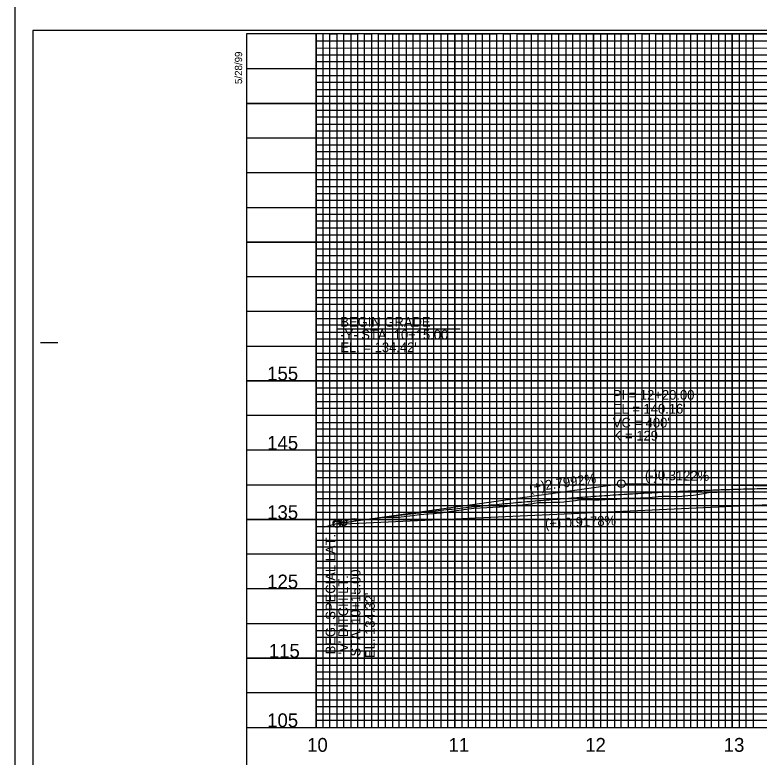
# Model space of a CAD drawing. Extents: x 573468 to 580768, y -57414 to -51768.
# Drawn here: x 578678 to 579215, y -54660 to -54125 of the extents above; entities that cross this region are included whole.
import ezdxf

# ---------------------------------------------------------------- set-up
doc = ezdxf.new("R2010")
doc.units = 0
for name, color, linetype in [('Exist Vertical Profile Ground Line', 7, 'Continuous'), ('Exist Vertical Profile Horizontal Axis Label Major', 7, 'Continuous'), ('Exist Vertical Profile Vertical Axis Label', 7, 'Continuous'), ('Prop Grid Mask', 7, 'Continuous'), ('Prop PFL Text', 7, 'Continuous'), ('Prop Vertical Profile Curve Label', 7, 'Continuous'), ('Prop Vertical Profile Ditch Grade Left', 7, 'Continuous'), ('Prop Vertical Profile Ditch Grade Left Label', 7, 'Continuous'), ('Prop Vertical Profile Grade', 7, 'Continuous'), ('Prop Vertical Profile Grade Label', 7, 'Continuous'), ('Prop VPI Label', 7, 'Continuous'), ('Sheet Cutting Line CELL', 7, 'Continuous'), ('Sheet DOT Grid CELL', 7, 'Continuous'), ('Sheet Layout Profile Border Port 1', 7, 'Continuous'), ('Sheet Plot Border Inside CELL', 7, 'Continuous'), ('Sheet Plot Border Outside CELL', 7, 'Continuous'), ('Sheet Profile CELL', 7, 'Continuous'), ('Sheet Profile Grid Major CELL', 7, 'Continuous'), ('Sheet Profile Grid Middle CELL', 7, 'Continuous'), ('Sheet Profile Grid Minor CELL', 7, 'Continuous')]:
    doc.layers.add(name, color=color, linetype=linetype)

msp = doc.modelspace()

# ---------------------------------------------------------------- linework, layer by layer
at = {"layer": 'Exist Vertical Profile Ground Line'}
msp.add_lwpolyline([(578895.21, -54493.46), (578895.85, -54493.47), (578901.67, -54493.94), (578908.48, -54491.97), (578920.94, -54488.12), (578922.63, -54487.88), (578926.71, -54488.36), (578933.83, -54487.97), (578936.58, -54487.74), (578938.64, -54487.62), (578939.29, -54487.52), (578942.98, -54486.97), (578954.34, -54486.84), (578964.93, -54485.71), (578969.46, -54485.07), (578979.55, -54484.18), (578984.58, -54483.76), (578986.86, -54483.62), (578992.92, -54482.56), (579008.86, -54480.34), (579018.41, -54479.87), (579022.67, -54479.67), (579026.92, -54479.46), (579027.71, -54479.42), (579030.86, -54479.24), (579031.18, -54479.19), (579034.6, -54478.75), (579035.43, -54478.67), (579039.68, -54478.28), (579043.94, -54477.88), (579048.19, -54477.48), (579050.77, -54477.24), (579052.45, -54476.9), (579055.59, -54476.26), (579056.7, -54476.25), (579060.96, -54476.19), (579065.21, -54476.13), (579069.46, -54476.07), (579070.81, -54476.05), (579073.72, -54475.73), (579077.97, -54475.28), (579079.81, -54475.08), (579082.23, -54474.75), (579085.92, -54474.26), (579086.48, -54474.26), (579087.34, -54474.25), (579090.13, -54474.23), (579090.74, -54474.25), (579094.99, -54474.36), (579096.22, -54474.39), (579099.24, -54474.29), (579101.58, -54474.21), (579103.5, -54474.15), (579107.75, -54474.02), (579111.34, -54473.91), (579112.01, -54473.86), (579115.05, -54473.6), (579116.26, -54473.35), (579116.95, -54473.21), (579120.52, -54473.21), (579124.77, -54473.21), (579125.98, -54473.21), (579129.02, -54473.05), (579131.17, -54472.94), (579133.28, -54472.85), (579133.85, -54472.83), (579137.53, -54472.46), (579141.79, -54472.04), (579145.34, -54471.69), (579146.04, -54471.7), (579150.3, -54471.8), (579154.55, -54471.89), (579156.1, -54471.93), (579158.8, -54471.68), (579163.06, -54471.29), (579167.31, -54470.91), (579168.97, -54470.76), (579171.57, -54470.32), (579175.82, -54469.6), (579179.08, -54468.86), (579180.08, -54468.84), (579184.33, -54468.76), (579188.58, -54468.69), (579190.03, -54468.66), (579192.84, -54468.67), (579197.09, -54468.68), (579201.35, -54468.69), (579202.27, -54468.7), (579205.6, -54468.58), (579209.86, -54468.44), (579211.27, -54468.39), (579214.11, -54468.59), (579218.36, -54468.89)], dxfattribs=at)
at = {"layer": 'Prop Grid Mask'}
msp.add_lwpolyline([(579095.21, -54388.55), (579195.21, -54388.55), (579195.21, -54438.55), (579095.21, -54438.55)], close=True, dxfattribs=at)
at = {"layer": 'Prop PFL Text'}
for q in [(578999.13, -54351.04), (578910.21, -54488.68)]:
    msp.add_line((578910.21, -54351.04), q, dxfattribs=at)
at = {"layer": 'Prop Vertical Profile Curve Label'}
msp.add_circle((578915.21, -54490.73), 2.25, dxfattribs=at)
at = {"layer": 'Prop Vertical Profile Ditch Grade Left'}
msp.add_line((578910.21, -54491.95), (579275.21, -54475.2), dxfattribs=at)
at = {"layer": 'Prop Vertical Profile Ditch Grade Left Label'}
msp.add_line((578910.21, -54491.95), (578910.21, -54587.95), dxfattribs=at)
msp.add_circle((578910.21, -54491.95), 2.25, dxfattribs=at)
at = {"layer": 'Prop Vertical Profile Grade'}
msp.add_line((578910.21, -54491.43), (578915.21, -54490.73), dxfattribs=at)
msp.add_spline([(578915.21, -54490.73), (578923.21, -54489.63), (578931.21, -54488.54), (578939.21, -54487.49), (578947.21, -54486.45), (578955.21, -54485.45), (578963.21, -54484.46), (578971.21, -54483.51), (578979.21, -54482.57), (578987.21, -54481.66), (578995.21, -54480.78), (579003.21, -54479.92), (579011.21, -54479.09), (579019.21, -54478.28), (579027.21, -54477.5), (579035.21, -54476.74), (579043.21, -54476), (579051.21, -54475.3), (579059.21, -54474.61), (579067.21, -54473.95), (579075.21, -54473.32), (579083.21, -54472.71), (579091.21, -54472.12), (579099.21, -54471.56), (579107.21, -54471.03), (579115.21, -54470.52), (579123.21, -54470.03), (579131.21, -54469.57), (579139.21, -54469.14), (579147.21, -54468.73), (579155.21, -54468.34), (579163.21, -54467.98), (579171.21, -54467.65), (579179.21, -54467.34), (579187.21, -54467.05), (579195.21, -54466.79), (579203.21, -54466.55), (579211.21, -54466.34), (579219.21, -54466.16), (579227.21, -54465.99), (579235.21, -54465.86), (579243.21, -54465.75), (579251.21, -54465.66), (579259.21, -54465.6), (579267.21, -54465.56), (579275.21, -54465.55), (579283.21, -54465.56), (579291.21, -54465.6), (579299.21, -54465.66), (579307.21, -54465.75), (579315.21, -54465.86)], degree=3, dxfattribs=at)
at = {"layer": 'Prop VPI Label'}
for p, q in [((578915.21, -54490.73), (579112.49, -54463.12)), ((579315.21, -54465.86), (579117.96, -54462.78))]:
    msp.add_line(p, q, dxfattribs=at)
for centre in [(579115.21, -54462.74), (578910.21, -54491.43)]:
    msp.add_circle(centre, 2.75, dxfattribs=at)
at = {"layer": 'Sheet Cutting Line CELL'}
msp.add_line((578678.21, -54113.55), (578678.21, -55213.55), dxfattribs=at)
at = {"layer": 'Sheet DOT Grid CELL'}
for p, q in [((578895.21, -54638.55), (578895.21, -54138.55)), ((578945.21, -54638.55), (578945.21, -54138.55)), ((578995.21, -54638.55), (578995.21, -54138.55)), ((579045.21, -54638.55), (579045.21, -54138.55)), ((579095.21, -54638.55), (579095.21, -54138.55)), ((579145.21, -54638.55), (579145.21, -54138.55)), ((579195.21, -54638.55), (579195.21, -54138.55)), ((580145.16, -54188.55), (578845.21, -54188.55)), ((580145.16, -54238.55), (578845.21, -54238.55)), ((580345.21, -54288.55), (578845.21, -54288.55)), ((580345.21, -54338.55), (578845.21, -54338.55)), ((580345.21, -54388.55), (578845.21, -54388.55)), ((580345.21, -54438.55), (578845.21, -54438.55)), ((580345.21, -54488.55), (578845.21, -54488.55)), ((580345.21, -54538.55), (578845.21, -54538.55)), ((580345.21, -54588.55), (578845.21, -54588.55))]:
    msp.add_line(p, q, dxfattribs=at)
at = {"layer": 'Sheet Layout Profile Border Port 1'}
msp.add_lwpolyline([(578895.21, -54138.55), (578895.21, -54638.55), (580295.21, -54638.55), (580295.21, -54276.1), (580145.16, -54276.1), (580145.16, -54138.55)], close=True, dxfattribs=at)
at = {"layer": 'Sheet Plot Border Inside CELL'}
msp.add_lwpolyline([(578691.21, -55191.1), (580357.71, -55191.1), (580357.71, -54136), (578691.21, -54136)], close=True, dxfattribs=at)
at = {"layer": 'Sheet Plot Border Outside CELL'}
msp.add_lwpolyline([(578678.21, -55213.55), (580362.21, -55213.55), (580362.21, -54113.55), (578678.21, -54113.55)], close=True, dxfattribs=at)
at = {"layer": 'Sheet Profile CELL'}
for p, q in [((578696.71, -54361.05), (578709.21, -54361.05)), ((578845.21, -54638.55), (580345.21, -54638.55))]:
    msp.add_line(p, q, dxfattribs=at)
msp.add_lwpolyline([(580345.21, -54138.55), (578845.21, -54138.55), (578845.21, -55188.55), (580345.21, -55188.55)], close=True, dxfattribs=at)
at = {"layer": 'Sheet Profile Grid Major CELL'}
for points in [[(578895.21, -54138.55), (578895.21, -54638.55), (578945.21, -54638.55), (578945.21, -54138.55), (578995.21, -54138.55), (578995.21, -54638.55), (579045.21, -54638.55), (579045.21, -54138.55), (579095.21, -54138.55), (579095.21, -54638.55), (579145.21, -54638.55), (579145.21, -54138.55), (579195.21, -54138.55), (579195.21, -54638.55), (579245.21, -54638.55)], [(578845.21, -54188.55), (580145.21, -54188.55)], [(580145.21, -54238.55), (578845.21, -54238.55), (578845.21, -54288.55), (580345.21, -54288.55)], [(580345.21, -54338.55), (578845.21, -54338.55), (578845.21, -54388.55), (580345.21, -54388.55)], [(580345.21, -54438.55), (578845.21, -54438.55), (578845.21, -54488.55), (580345.21, -54488.55)], [(580345.21, -54538.55), (578845.21, -54538.55), (578845.21, -54538.55), (578845.21, -54588.55), (580345.21, -54588.55)]]:
    msp.add_lwpolyline(points, dxfattribs=at)
at = {"layer": 'Sheet Profile Grid Middle CELL'}
msp.add_line((578845.21, -54163.55), (580145.16, -54163.55), dxfattribs=at)
for points in [[(578920.21, -54138.55), (578920.21, -54638.55), (578970.21, -54638.55), (578970.21, -54138.55), (579020.21, -54138.55), (579020.21, -54638.55), (579070.21, -54638.55), (579070.21, -54138.55), (579120.21, -54138.55), (579120.21, -54638.55), (579170.21, -54638.55), (579170.21, -54138.55), (579220.21, -54138.55)], [(580145.21, -54213.55), (578845.21, -54213.55), (578845.21, -54263.55), (580145.21, -54263.55)], [(580345.21, -54313.55), (578845.21, -54313.55), (578845.21, -54363.55), (580170.21, -54363.55)], [(580345.21, -54413.55), (578845.21, -54413.55), (578845.21, -54463.55), (580345.21, -54463.55)], [(580345.21, -54513.55), (578845.21, -54513.55), (578845.21, -54563.55), (580345.21, -54563.55)], [(580345.21, -54613.55), (578845.21, -54613.55)]]:
    msp.add_lwpolyline(points, dxfattribs=at)
at = {"layer": 'Sheet Profile Grid Minor CELL'}
for p, q in [((578895.21, -54143.55), (580145.21, -54143.55)), ((578895.21, -54148.55), (578895.21, -54148.55)), ((580145.21, -54148.55), (578895.21, -54148.9)), ((578895.21, -54153.55), (580145.21, -54153.55)), ((580145.16, -54273.55), (578895.21, -54273.55)), ((580295.21, -54278.55), (578895.21, -54278.55)), ((580295.21, -54283.55), (578895.21, -54283.55)), ((578895.21, -54293.55), (580295.21, -54293.55)), ((580295.21, -54298.55), (578895.21, -54298.55)), ((578895.21, -54303.55), (580295.21, -54303.55)), ((580295.21, -54323.55), (578895.21, -54323.55)), ((578895.21, -54328.55), (580295.21, -54328.55)), ((580295.21, -54348.55), (578895.21, -54348.55)), ((578895.21, -54353.55), (580295.21, -54353.55)), ((580295.21, -54373.55), (578895.21, -54373.55)), ((578895.21, -54378.55), (580295.21, -54378.55)), ((580295.21, -54383.55), (578895.21, -54383.55)), ((578895.21, -54393.55), (580295.21, -54393.55)), ((580295.21, -54398.55), (578895.21, -54398.55)), ((578895.21, -54403.55), (580295.21, -54403.55)), ((580295.21, -54408.55), (578895.21, -54408.55)), ((578895.21, -54418.55), (580295.21, -54418.55)), ((580295.21, -54423.55), (578895.21, -54423.55)), ((578895.21, -54428.55), (580295.21, -54428.55)), ((580295.21, -54433.55), (578895.21, -54433.55)), ((578895.21, -54443.55), (580295.21, -54443.55)), ((580295.21, -54448.55), (578895.21, -54448.55)), ((578895.21, -54453.55), (580295.21, -54453.55)), ((580295.21, -54458.55), (578895.21, -54458.55)), ((578895.21, -54468.55), (580295.21, -54468.55)), ((580295.21, -54473.55), (578895.21, -54473.55)), ((578895.21, -54478.55), (580295.21, -54478.55)), ((580295.21, -54483.55), (578895.21, -54483.55)), ((578895.21, -54493.55), (580295.21, -54493.55)), ((580295.21, -54498.55), (578895.21, -54498.55)), ((578895.21, -54503.55), (580295.21, -54503.55)), ((580295.21, -54508.55), (578895.21, -54508.55)), ((578895.21, -54518.55), (580295.21, -54518.55)), ((580295.21, -54523.55), (578895.21, -54523.55)), ((580295.21, -54528.55), (578895.21, -54528.55)), ((580295.21, -54533.55), (578895.21, -54533.55)), ((578895.21, -54543.55), (580295.21, -54543.55)), ((580295.21, -54548.55), (578895.21, -54548.55)), ((578895.21, -54553.55), (580295.21, -54553.55)), ((580295.21, -54558.55), (578895.21, -54558.55)), ((578895.21, -54568.55), (580295.21, -54568.55)), ((580295.21, -54573.55), (578895.21, -54573.55)), ((578895.21, -54578.55), (580295.21, -54578.55)), ((580295.21, -54583.55), (578895.21, -54583.55)), ((578895.21, -54593.55), (580295.21, -54593.55)), ((580295.21, -54598.55), (578895.21, -54598.55)), ((578895.21, -54603.55), (580295.21, -54603.55)), ((580295.21, -54608.55), (578895.21, -54608.55)), ((578895.21, -54618.55), (580295.21, -54618.55)), ((580295.21, -54623.55), (578895.21, -54623.55)), ((578895.21, -54628.55), (580295.21, -54628.55))]:
    msp.add_line(p, q, dxfattribs=at)
for points in [[(578900.21, -54138.55), (578900.21, -54638.55), (578905.21, -54638.55), (578905.21, -54138.55), (578910.21, -54138.55), (578910.21, -54638.55), (578915.21, -54638.55), (578915.21, -54138.55), (578925.21, -54138.55), (578925.21, -54638.55), (578930.21, -54638.55), (578930.21, -54138.55), (578935.21, -54138.55), (578935.21, -54638.55), (578940.21, -54638.55), (578950.21, -54638.55), (578955.21, -54638.55), (578955.21, -54138.55), (578960.21, -54138.55), (578960.21, -54638.55), (578965.21, -54638.55), (578965.21, -54138.55), (578975.21, -54138.55), (578975.21, -54638.55), (578980.21, -54638.55), (578980.21, -54138.55), (578985.21, -54138.55), (578985.21, -54638.55), (578990.21, -54638.55), (578990.21, -54138.55), (579000.21, -54138.55), (579000.21, -54638.55), (579005.21, -54638.55), (579005.21, -54138.55), (579010.21, -54138.55), (579010.21, -54638.55), (579015.21, -54638.55), (579015.21, -54138.55), (579025.21, -54138.55), (579025.21, -54638.55), (579030.21, -54638.55), (579030.21, -54138.55), (579035.21, -54138.55), (579035.21, -54638.55), (579040.21, -54638.55), (579040.21, -54138.55), (579050.21, -54138.55), (579050.21, -54638.55), (579055.21, -54638.55), (579055.21, -54138.55), (579060.21, -54138.55), (579060.21, -54638.55), (579065.21, -54638.55), (579065.21, -54138.55), (579075.21, -54138.55), (579075.21, -54638.55), (579080.21, -54638.55), (579080.21, -54138.55), (579085.21, -54138.55), (579085.21, -54638.55), (579090.21, -54638.55), (579090.21, -54138.55), (579100.21, -54138.55), (579100.21, -54638.55), (579105.21, -54638.55), (579105.21, -54138.55), (579110.21, -54138.55), (579110.21, -54638.55)], [(578940.21, -54638.55), (578940.21, -54138.55), (578950.21, -54138.55), (578950.21, -54638.55)], [(579110.21, -54638.55), (579115.21, -54638.55), (579115.21, -54138.55), (579125.21, -54138.55), (579125.21, -54638.55), (579130.21, -54638.55), (579130.21, -54138.55), (579135.21, -54138.55), (579135.21, -54638.55), (579140.21, -54638.55), (579140.21, -54138.55), (579150.21, -54138.55), (579150.21, -54638.55), (579155.21, -54638.55), (579155.21, -54138.55), (579160.21, -54138.55), (579160.21, -54638.55), (579165.21, -54638.55), (579165.21, -54138.55), (579175.21, -54138.55), (579175.21, -54638.55), (579180.21, -54638.55), (579180.21, -54138.55), (579185.21, -54138.55), (579185.21, -54638.55), (579190.21, -54638.55), (579190.21, -54138.55), (579200.21, -54138.55), (579200.21, -54638.55), (579205.21, -54638.55), (579205.21, -54138.55), (579210.21, -54138.55), (579210.21, -54638.55), (579215.21, -54638.55)], [(580145.21, -54158.55), (578895.21, -54158.55), (578895.21, -54168.55), (580145.21, -54168.55)], [(580145.16, -54173.55), (578895.21, -54173.55), (578895.21, -54178.55), (580145.21, -54178.55)], [(580145.21, -54183.55), (578895.21, -54183.55), (578895.21, -54193.55), (580145.21, -54193.55)], [(580145.21, -54198.55), (578895.21, -54198.55), (578895.21, -54203.55), (580145.21, -54203.55)], [(580145.21, -54208.55), (578895.21, -54208.55), (578895.21, -54218.55), (580145.21, -54218.55)], [(580145.21, -54223.55), (578895.21, -54223.55), (578895.21, -54228.55), (580145.21, -54228.55)], [(580145.21, -54233.55), (578895.21, -54233.55), (578895.21, -54243.55), (580145.21, -54243.55)], [(580145.21, -54248.65), (578895.31, -54248.65), (578895.31, -54253.55), (580145.21, -54253.55)], [(580145.21, -54258.55), (578895.21, -54258.55), (578895.21, -54268.55), (580145.21, -54268.55)], [(580295.21, -54308.55), (578895.21, -54308.55), (578895.21, -54318.55), (580295.21, -54318.55)], [(580295.21, -54333.55), (578895.21, -54333.55), (578895.21, -54343.55), (580295.21, -54343.55)], [(580295.21, -54358.55), (578895.21, -54358.55), (578895.21, -54368.55), (580295.21, -54368.55)], [(580295.21, -54633.55), (578895.21, -54633.55)]]:
    msp.add_lwpolyline(points, dxfattribs=at)

# ---------------------------------------------------------------- texts
at = {"layer": 'Exist Vertical Profile Horizontal Axis Label Major'}
for s, p in [('10', (578888.8, -54656.05)), ('11', (578990.64, -54656.05)), ('12', (579089.19, -54656.05)), ('13', (579189.02, -54656.05))]:
    msp.add_text(s, height=10, dxfattribs=at).set_placement(p)
at = {"layer": 'Exist Vertical Profile Vertical Axis Label'}
for s, p in [('155', (578860, -54388.3)), ('145', (578860, -54438.3)), ('135', (578860, -54488.3)), ('125', (578860, -54538.3)), ('115', (578861.2, -54588.3)), ('105', (578860, -54638.3))]:
    msp.add_text(s, height=10, dxfattribs=at).set_placement(p)
at = {"layer": 'Prop PFL Text'}
for s, p in [('BEGIN GRADE', (578912.73, -54349.59)), ('-Y- STA. 10+15.00', (578912.73, -54358.77)), ("EL. = 134.42'", (578912.73, -54367.94))]:
    msp.add_text(s, height=7, dxfattribs=at).set_placement(p)
at = {"layer": 'Prop Vertical Profile Curve Label'}
for s, p in [("VC = 400'", (579109.08, -54422.22)), ('K = 129', (579109.08, -54431.65))]:
    msp.add_text(s, height=7, dxfattribs=at).set_placement(p)
at = {"layer": 'Prop Vertical Profile Ditch Grade Left'}
for s, rotation, p in [('(+) 0.9178%', 2.6275, (579060.37, -54494.99)), ("EL. 134.32'", 90, (578937.59, -54588.42))]:
    msp.add_text(s, height=7, rotation=rotation, dxfattribs=at).set_placement(p)
at = {"layer": 'Prop Vertical Profile Ditch Grade Left Label'}
for s, p in [('BEG. SPECIAL LAT.', (578909.16, -54585.81)), ('STA. 10+15.00', (578927.25, -54587.28)), ("'V' DITCH LT.", (578918.34, -54585.81))]:
    msp.add_text(s, height=7, rotation=90, dxfattribs=at).set_placement(p)
at = {"layer": 'Prop Vertical Profile Grade Label'}
for s, rotation, p in [('(+)2.7992%', 7.9675, (579049.22, -54468.95)), ('(-)0.3122%', 359.1058, (579132.17, -54460.01))]:
    msp.add_text(s, height=7, rotation=rotation, dxfattribs=at).set_placement(p)
at = {"layer": 'Prop VPI Label'}
for s, p in [('PI = 12+20.00', (579109.08, -54402.22)), ("EL = 140.16'", (579109.08, -54412.22))]:
    msp.add_text(s, height=7, dxfattribs=at).set_placement(p)
at = {"layer": 'Sheet Profile CELL'}
msp.add_text('5/28/99', height=5.25, rotation=90, dxfattribs=at).set_placement((578841.98, -54174.64))

doc.saveas('drawing.dxf')
